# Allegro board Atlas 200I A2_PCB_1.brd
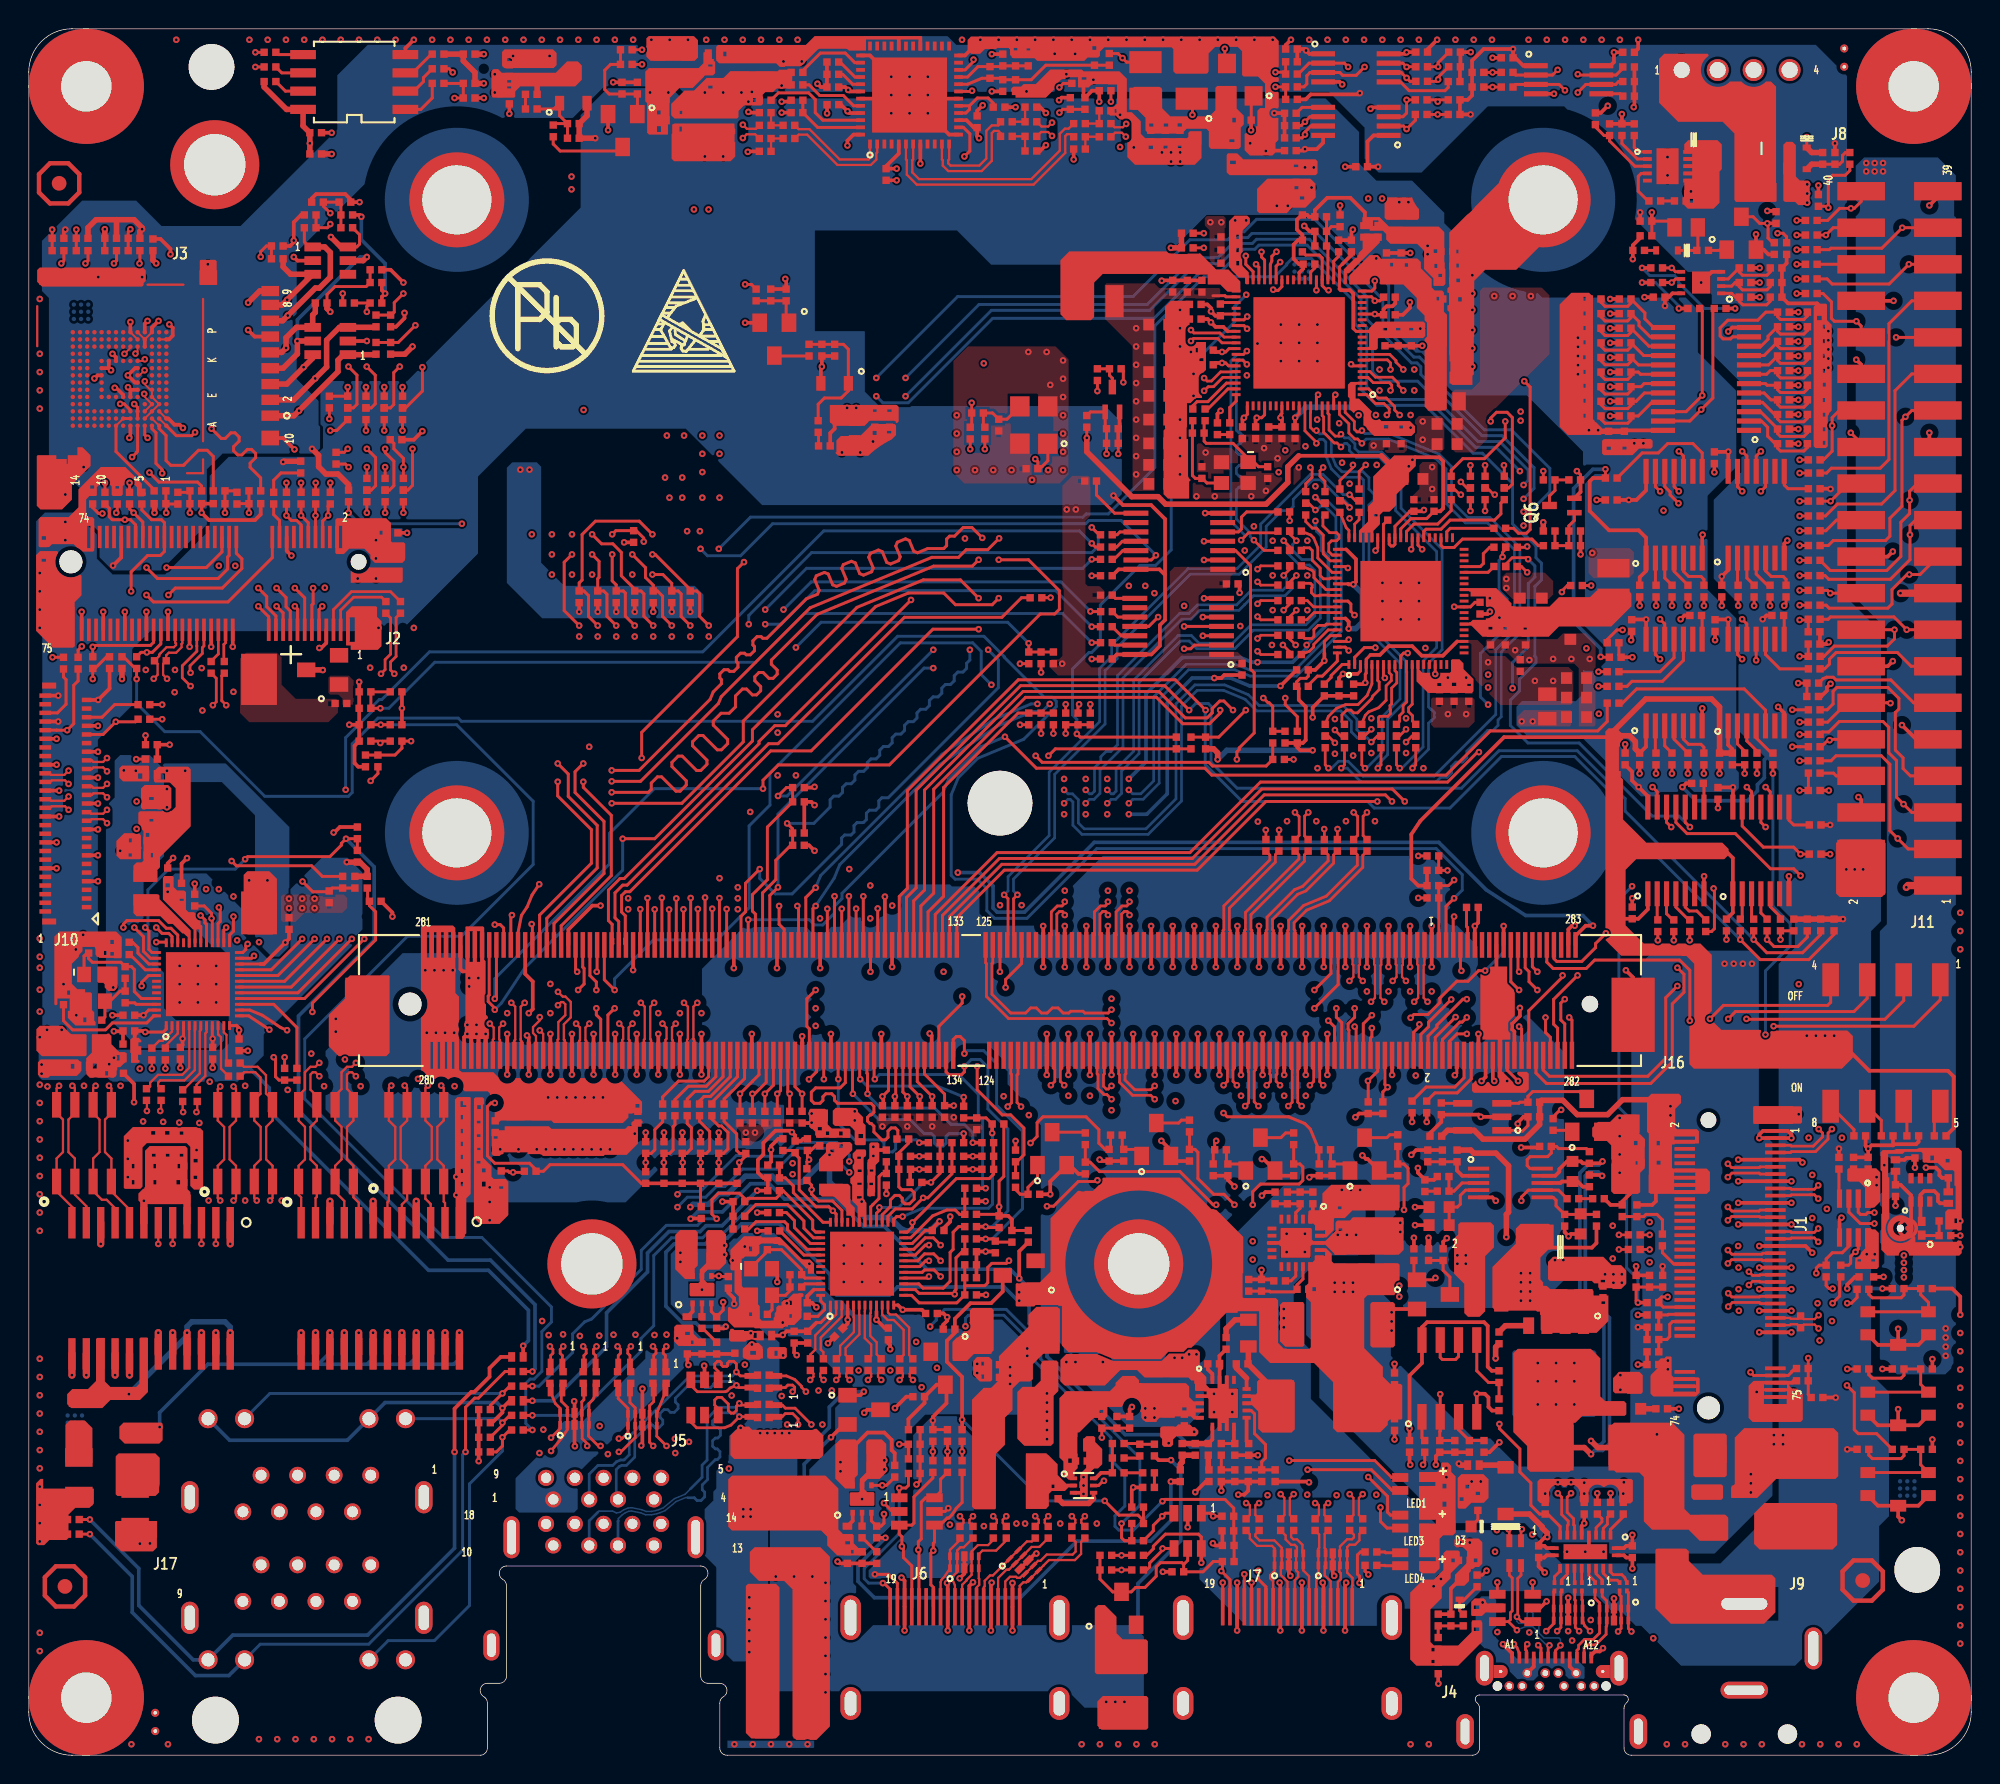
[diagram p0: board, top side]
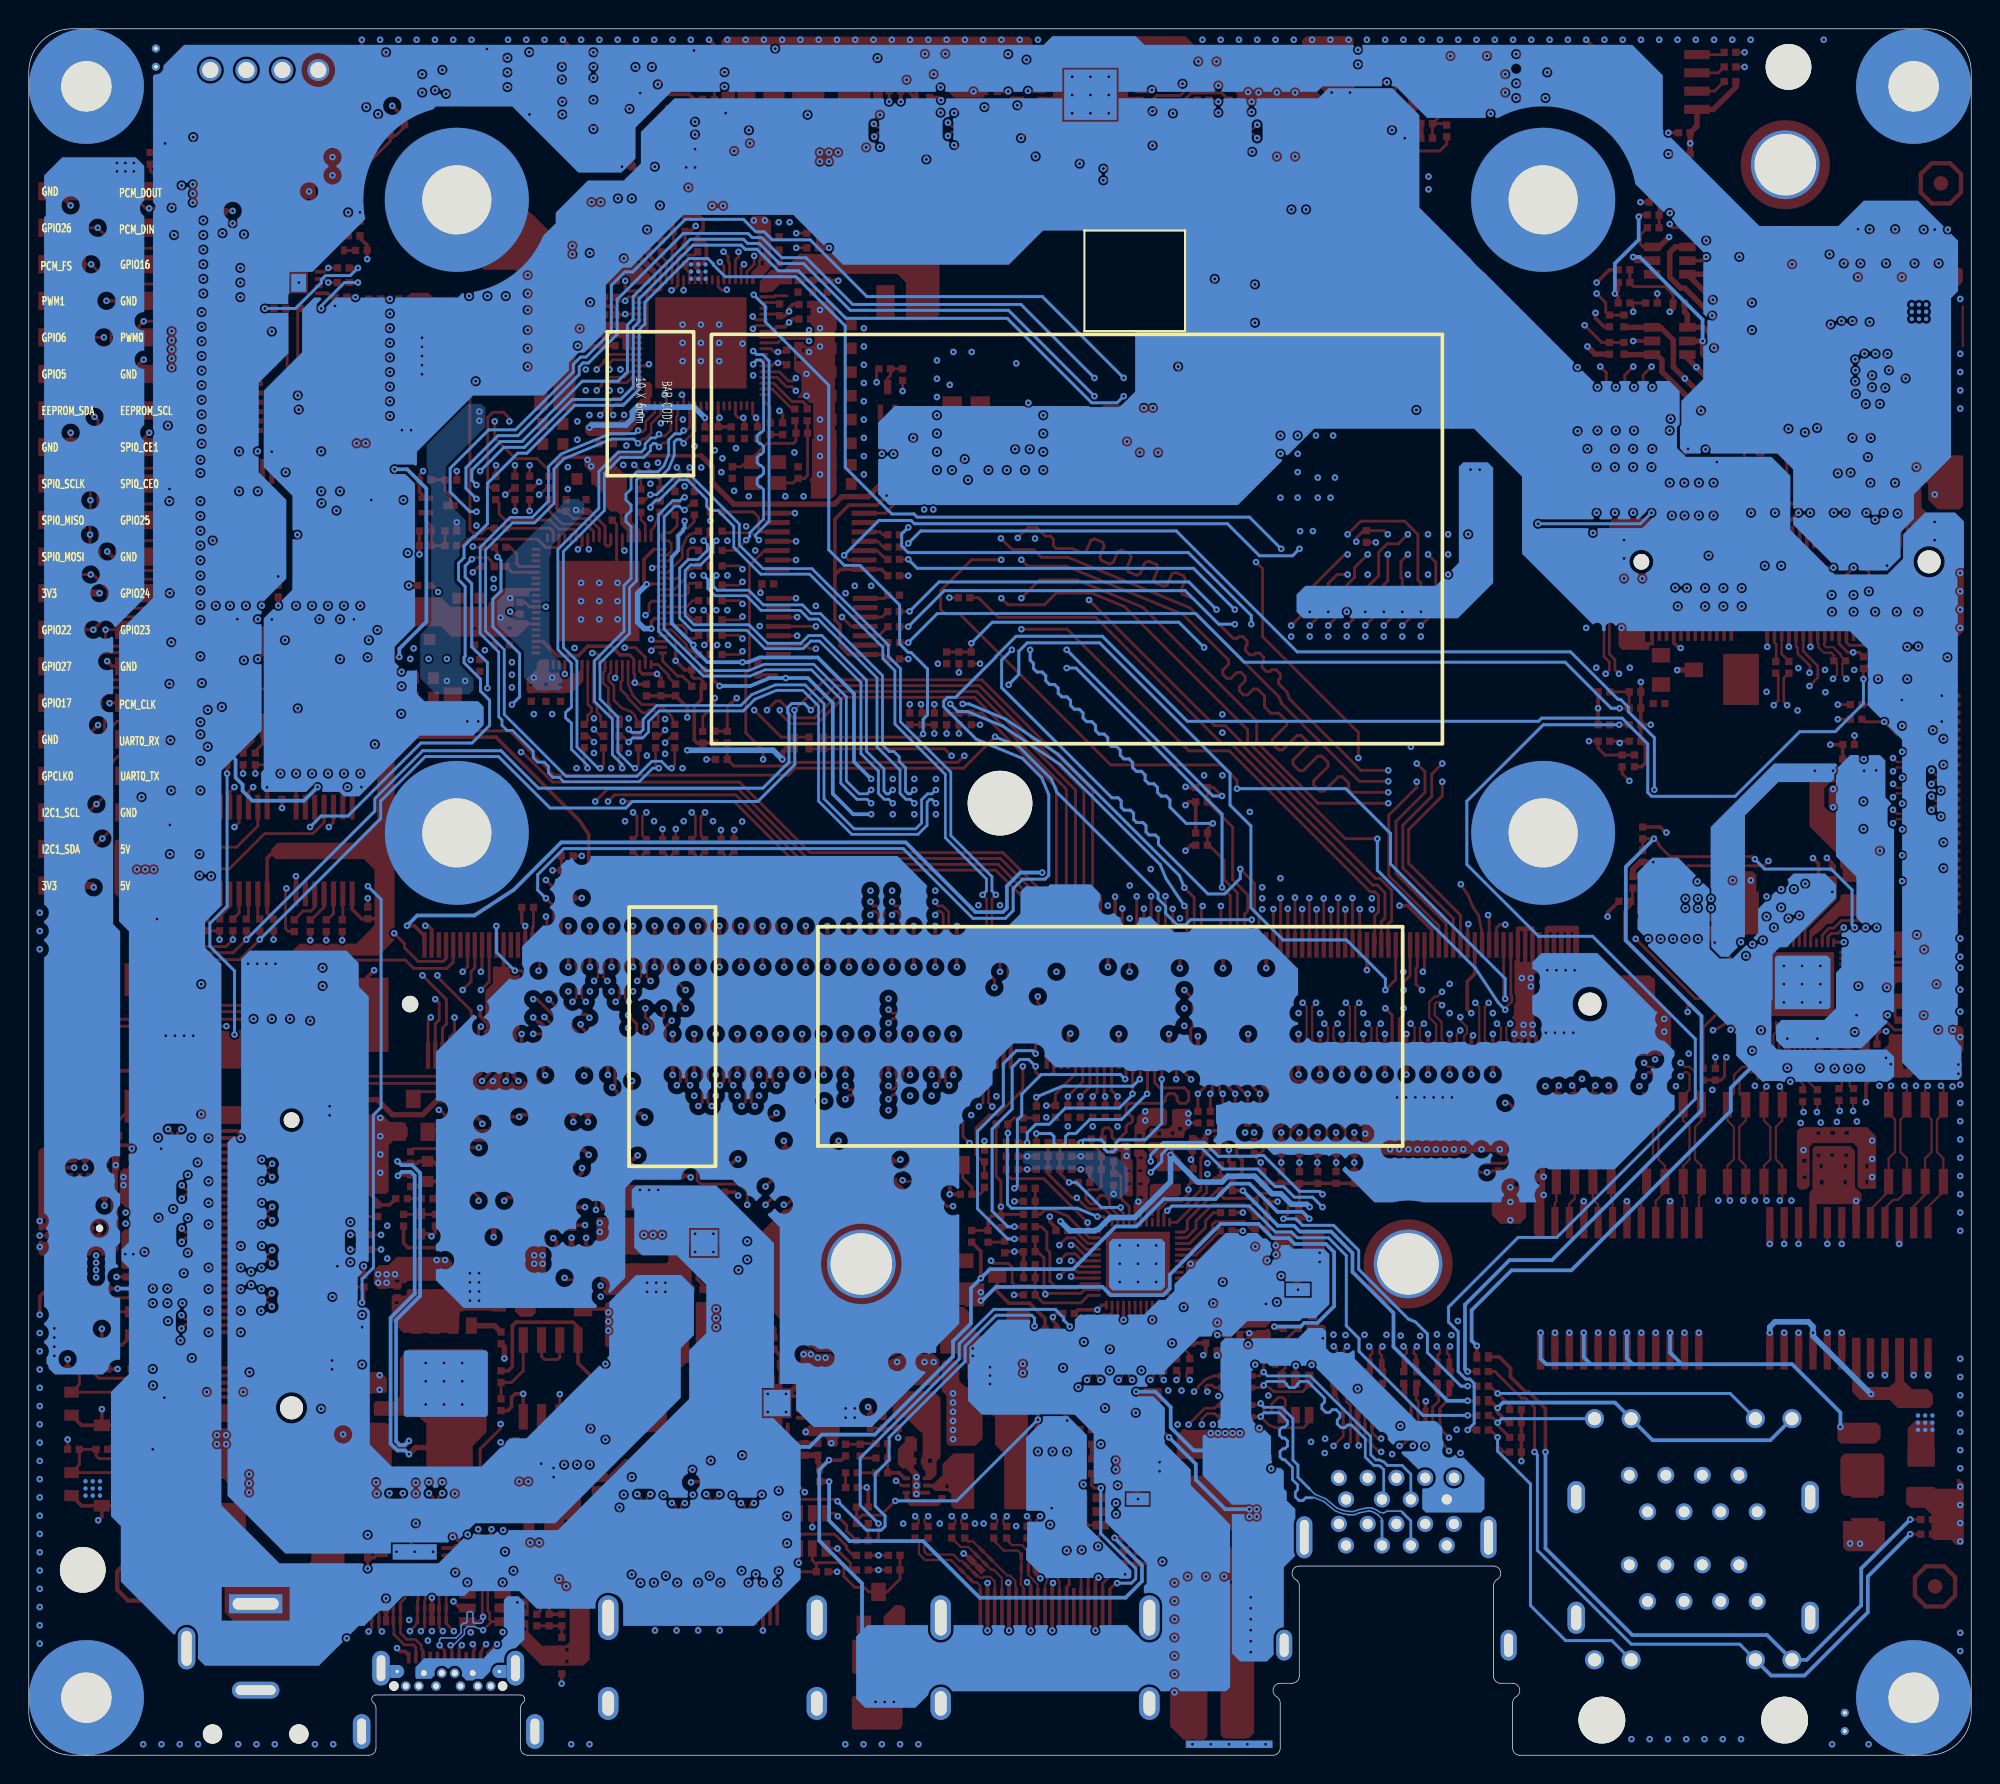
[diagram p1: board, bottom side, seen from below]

Outline 135 x 120 mm; copper layers: TOP, ART02, ART03, ART04, ART05, BOTTOM. Coordinates in mm from the lower left corner of the outline.
Outline path: 0,117 0,3 arc(0.88,0.88) 3,0 31.38,0 arc(31.73,0.15) 31.87,0.5 31.87,3.63 arc(31.81,3.88) 31.63,4.07 arc(31.39,4.63) 31.87,5 32.7,5 arc(33.05,5.15) 33.2,5.5 33.2,11.78 arc(33.13,12.03) 32.95,12.22 arc(32.72,12.78) 33.2,13.15 46.7,13.15 arc(47.18,12.78) 46.95,12.22 arc(46.77,12.03) 46.7,11.78 46.7,5.5 arc(46.85,5.15) 47.2,5 48.02,5 arc(48.51,4.63) 48.27,4.07 arc(48.09,3.88) 48.02,3.63 48.02,0.5 arc(48.17,0.15) 48.52,0 100.33,0 arc(100.68,0.15) 100.83,0.5 100.83,3.27 arc(100.78,3.48) 100.64,3.66 arc(100.55,3.99) 100.83,4.19 110.87,4.19 arc(111.15,3.99) 111.06,3.66 arc(110.92,3.48) 110.87,3.27 110.87,0.5 arc(111.02,0.15) 111.37,0 132,0 arc(134.12,0.88) 135,3 135,117 arc(134.12,119.12) 132,120 3,120 arc(0.88,119.12) 0,117

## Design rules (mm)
constraint set DEFAULT: min track width 0.203
net group $12N40858: nets $12N40858 $12N40901
net group $47N4481: nets $47N4481 /CLKREQ_WIFI
net group $47N43343: nets $47N43343 USB2_2_DP
net group $47N43374: nets $47N43374 USB2_2_DN
net group /EMMC_RESET: nets /EMMC_RESET /EMMC_RESET_R
net group /LED_PHY0_ACT: nets $19N46347 /LED_PHY0_ACT
net group /LED_PHY0_LINK: nets $19N73517 /LED_PHY0_LINK
net group /LED_PHY1_ACT: nets $19N48970 /LED_PHY1_ACT
net group /LED_PHY1_LINK: nets $19N48969 /LED_PHY1_LINK
net group /PERST_M2: nets $51N193077 /PERST_M2
net group /PERST_M2_R: nets $46N95508 /PERST_M2_R
net group /PERST_WIFI: nets $51N185068 /PERST_WIFI
net group /PERST_WIFI_R: nets $51N185799 /PERST_WIFI_R
net group /PEWAKE_WIFI: nets $51N189030 /PEWAKE_WIFI
net group /WAKE_PHY0: nets $51N189029 /WAKE_PHY0
net group /WAKE_PHY1: nets $51N189028 /WAKE_PHY1
net group /WAKE_UART3: nets $47N36111 /WAKE_UART3
net group AC_MICBIAS0: nets $16N50739 AC_MICBIAS0
net group CARD_DETECT: nets CARD_DETECT SDIO_DETECT
net group CLK_100M_OSC: nets $17N59162 CLK_100M_OSC
net group DEVSLP_M2: nets $46N95153 DEVSLP_M2
net group DIFFUSB2_1: nets USB2_1_DN USB2_1_DP
net group DIFFUSB2_3: nets USB2_3_DN USB2_3_DP
net group DIFFUSB2_3_HUB0: nets USB2_3_HUB0_DN USB2_3_HUB0_DP
net group DIFFUSB2_3_HUB1: nets USB2_3_HUB1_DN USB2_3_HUB1_DP
net group DIFFUSB3_2_TX: nets USB3_2_TX_N USB3_2_TX_P
net group DIFFUSB3_3_RX_HUB0: nets USB3_3_RX_HUB0_N USB3_3_RX_HUB0_P
net group DIFFUSB3_3_RX_HUB1: nets USB3_3_RX_HUB1_N USB3_3_RX_HUB1_P
net group DIFFUSB3_3_TX_HUB0: nets USB3_3_TX_HUB0_N USB3_3_TX_HUB0_P
net group DIFFUSB3_3_TX_HUB1: nets USB3_3_TX_HUB1_N USB3_3_TX_HUB1_P
net group DIFFUSB3_3_TYPEA1_HUB0_TX1: nets USB3_3_TYPEA1_HUB0_TX1_N USB3_3_TYPEA1_HUB0_TX1_P
net group DIFFUSB3_3_TYPEA1_HUB1_RX1: nets USB3_3_TYPEA1_HUB1_RX1_N USB3_3_TYPEA1_HUB1_RX1_P
net group DIFFUSB3_3_TYPEA1_HUB1_TX1: nets USB3_3_TYPEA1_HUB1_TX1_N USB3_3_TYPEA1_HUB1_TX1_P
net group DIFFUSB3_3_TYPEA1_HUB_RX1: nets USB3_3_TYPEA1_HUB_RX1_N USB3_3_TYPEA1_HUB_RX1_P
net group DIFFUSB3_3_TYPEA2_HUB0_RX2: nets USB3_3_TYPEA2_HUB0_RX2_N USB3_3_TYPEA2_HUB0_RX2_P
net group DIFFUSB3_3_TYPEA2_HUB0_TX2: nets USB3_3_TYPEA2_HUB0_TX2_N USB3_3_TYPEA2_HUB0_TX2_P
net group DIFFUSB3_3_TYPEA2_HUB1_RX2: nets USB3_3_TYPEA2_HUB1_RX2_N USB3_3_TYPEA2_HUB1_RX2_P
net group DIFFUSB3_3_TYPEA2_HUB1_TX2: nets USB3_3_TYPEA2_HUB1_TX2_N USB3_3_TYPEA2_HUB1_TX2_P
net group DIFFUSB3_3_TYPEA2_HUB_RX2: nets USB3_3_TYPEA2_HUB_RX2_N USB3_3_TYPEA2_HUB_RX2_P
net group DIFFUSB3_3_TYPEA2_HUB_TX2: nets USB3_3_TYPEA2_HUB_TX2_N USB3_3_TYPEA2_HUB_TX2_P
net group DIFFUSB20_TYPEA2_HUB1: nets USB20_TYPEA2_HUB1_DN USB20_TYPEA2_HUB1_DP
net group DIFFUSB_TYPEC_CON: nets USB_TYPEC_CON_DN USB_TYPEC_CON_DP
net group DSI_I2C_INT: nets $51N189031 DSI_I2C_INT
net group DSI_I2C_INT_R: nets $49N38251 DSI_I2C_INT_R
net group FAN_STA: nets $18N13057 FAN_STA
net group GATE_24711: nets $20N81774 GATE_24711
net group GPIO13: nets $51N194833 GPIO13
net group GPIO16: nets $51N171792 GPIO16
net group GPIO17_3V3: nets $49N29598 GPIO17_3V3
net group GPIO22: nets $51N172159 GPIO22
net group GPIO22_3V3: nets $49N16355 GPIO22_3V3
net group GPIO23: nets $51N172500 GPIO23
net group GPIO23_3V3: nets $49N16315 GPIO23_3V3
net group GPIO24: nets $51N176455 GPIO24
net group GPIO24_3V3: nets $49N16316 GPIO24_3V3
net group GPIO25: nets $51N176454 GPIO25
net group GPIO26: nets $51N176453 GPIO26
net group GPIO26_3V3: nets $49N16328 GPIO26_3V3
net group GPIO27: nets $51N194878 GPIO27
net group HDMI0_CEC: nets HDMI0_CEC HDMI0_TX_CEC
net group HDMI0_SCL: nets HDMI0_SCL HDMI0_TX_DDC_SCL_C
net group HDMI0_SDA: nets HDMI0_SDA HDMI0_TX_DDC_SDA_C
net group HDMI0_TXC_N: nets HDMI0_TXC_C_N HDMI0_TXC_N
net group HDMI0_TXC_P: nets HDMI0_TXC_C_P HDMI0_TXC_P
net group HDMI1_CEC: nets HDMI1_CEC HDMI1_TX_CEC
net group HDMI1_SCL: nets HDMI1_SCL HDMI1_TX_DDC_SCL_C
net group HDMI1_SDA: nets HDMI1_SDA HDMI1_TX_DDC_SDA_C
net group HDMI1_TX0_C_N: nets HDMI1_TX0_C_N HDMI1_TX0_N
net group HDMI1_TX0_C_P: nets HDMI1_TX0_C_P HDMI1_TX0_P
net group HDMI1_TX1_C_N: nets HDMI1_TX1_C_N HDMI1_TX1_N
net group HDMI1_TX1_C_P: nets HDMI1_TX1_C_P HDMI1_TX1_P
net group HDMI1_TX2_C_N: nets HDMI1_TX2_C_N HDMI1_TX2_N
net group HDMI1_TX2_C_P: nets HDMI1_TX2_C_P HDMI1_TX2_P
net group HDMI1_TXC_C_N: nets HDMI1_TXC_C_N HDMI1_TXC_N
net group HDMI1_TXC_C_P: nets HDMI1_TXC_C_P HDMI1_TXC_P
net group I2C6_SCL: nets $49N16337 I2C6_SCL
net group I2C6_SDA: nets $49N16335 I2C6_SDA
net group I2C7_SCL: nets $49N18560 I2C7_SCL
net group I2C7_SCL_R: nets $49N16308 I2C7_SCL_R
net group I2C7_SDA: nets $49N18561 I2C7_SDA
net group I2C7_SDA_R: nets $49N16307 I2C7_SDA_R
net group I2S0_BCLK_R: nets $49N16347 I2S0_BCLK_R
net group I2S0_LRCK: nets $51N204476 I2S0_LRCK
net group I2S0_LRCK_R: nets $49N16344 I2S0_LRCK_R
net group I2S0_MCLK: nets $51N196013 I2S0_MCLK
net group I2S0_MISO: nets $51N204970 I2S0_MISO
net group I2S0_MISO_R: nets $49N16346 I2S0_MISO_R
net group I2S0_MOSI: nets $51N205764 I2S0_MOSI
net group I2S0_MOSI_R: nets $49N16348 I2S0_MOSI_R
net group I2S1_BCLK: nets $47N8328 I2S1_BCLK
net group I2S1_LRCK: nets $47N8362 I2S1_LRCK
net group I2S1_MCLK: nets $51N196011 I2S1_MCLK
net group I2S1_MCLK_R: nets $49N25997 I2S1_MCLK_R
net group I2S1_MISO: nets $47N12203 I2S1_MISO
net group I2S1_MOSI: nets $47N12239 I2S1_MOSI
net group LED_G: nets $45N7207 LED_G
net group LED_HEALTHY_G: nets $45N4598 LED_HEALTHY_G
net group LED_HEALTHY_R: nets $45N4597 LED_HEALTHY_R
net group LED_R: nets $45N7206 LED_R
net group M2_TYPE: nets $46N92195 M2_TYPE
net group MIPI_DSI_SCL: nets $49N18573 MIPI_DSI_SCL
net group MIPI_DSI_SCL_R: nets $49N8793 MIPI_DSI_SCL_R
net group MIPI_DSI_SDA: nets $49N18574 MIPI_DSI_SDA
net group MIPI_DSI_SDA_R: nets $49N8755 MIPI_DSI_SDA_R
net group MIPI_GPIO: nets $51N175745 MIPI_GPIO
net group MIPI_GPIO_R: nets $49N38048 MIPI_GPIO_R
net group PCIE_RX_N/SATA_B_P: nets PCIE_RX_N/SATA_B_P SERDES0_RX_N
net group PCIE_RX_P/SATA_B_N: nets PCIE_RX_P/SATA_B_N SERDES0_RX_P
net group PWM1: nets $51N193392 PWM1
net group PWM1_R: nets $49N16343 PWM1_R
net group RGMII0_MDCK: nets $7N42494 RGMII0_MDCK
net group RGMII0_MDIO: nets $7N42485 RGMII0_MDIO
net group RGMII0_RST: nets $51N184427 RGMII0_RST
net group RGMII0_RST_R: nets $51N185453 RGMII0_RST_R
net group RGMII0_RXCK: nets RGMII0_RXCK RGMII_CLK_PHY0
net group RGMII0_RXD0: nets RGMII0_RXD0 RGMII_PHY0_D0
net group RGMII0_RXD1: nets RGMII0_RXD1 RGMII_PHY0_D1
net group RGMII0_RXD2: nets RGMII0_RXD2 RGMII_PHY0_D2
net group RGMII0_RXD3: nets RGMII0_RXD3 RGMII_PHY0_D3
net group RGMII0_RXDV: nets RGMII0_RXDV RGMII_DV_PHY0
net group RGMII1_MDCK: nets $8N37120 RGMII1_MDCK
net group RGMII1_MDIO: nets $8N37111 RGMII1_MDIO
net group RGMII1_RST: nets $51N184426 RGMII1_RST
net group RGMII1_RST_R: nets $51N185452 RGMII1_RST_R
net group RGMII1_RXCK: nets RGMII1_RXCK RGMII_CLK_PHY1
net group RGMII1_RXD0: nets RGMII1_RXD0 RGMII_PHY1_D0
net group RGMII1_RXD1: nets RGMII1_RXD1 RGMII_PHY1_D1
net group RGMII1_RXD2: nets RGMII1_RXD2 RGMII_PHY1_D2
net group RGMII1_RXD3: nets RGMII1_RXD3 RGMII_PHY1_D3
net group RGMII1_RXDV: nets RGMII1_RXDV RGMII_DV_PHY1
net group SERDES1_RX: nets SERDES1_RX_N SERDES1_RX_P
net group SERDES2_RX: nets SERDES2_RX_N SERDES2_RX_P
net group SERDES3_RX: nets SERDES3_RX_N SERDES3_RX_P
net group SERDES4_RX: nets SERDES4_RX_N SERDES4_RX_P
net group SERDES4_TX_N: nets $47N40951 SERDES4_TX_N
net group SERDES4_TX_P: nets $47N40952 SERDES4_TX_P
net group SPI0_CLK: nets $51N199818 SPI0_CLK
net group SPI0_CLK_R: nets $49N16313 SPI0_CLK_R
net group SPI0_CS0: nets $51N198291 SPI0_CS0
net group SPI0_CS0_R: nets $49N16317 SPI0_CS0_R
net group SPI0_MISO: nets $51N199282 SPI0_MISO
net group SPI0_MISO_R: nets $49N16312 SPI0_MISO_R
net group SPI0_MOSI: nets $51N198558 SPI0_MOSI
net group SPI0_MOSI_R: nets $49N16311 SPI0_MOSI_R
net group SPI_CS_HUB: nets $56N3511 SPI_CS_HUB
net group SPI_MISO_HUB: nets $56N3501 SPI_MISO_HUB
net group SPI_MOSI_HUB: nets $56N3513 SPI_MOSI_HUB
net group SPI_SCK_HUB: nets $56N3505 SPI_SCK_HUB
net group SYS_RST_IN: nets SYS_RST_IN SYS_RST_IN_R
net group TAISHAN_POWEROFF_IN: nets TAISHAN_POWEROFF_IN TAISHAN_POWEROFF_IN_R
net group UART0_RX_R: nets $49N16309 UART0_RX_R
net group UART2_CTX: nets $51N196657 UART2_CTX
net group UART2_CTX_R: nets $49N34084 UART2_CTX_R
net group UART2_RTX: nets $51N196656 UART2_RTX
net group UART2_RTX_R: nets $49N34222 UART2_RTX_R
net group UART3_CTX: nets $47N4444 UART3_CTX
net group UART3_RTX: nets $47N18593 UART3_RTX
net group UART3_RX: nets $47N4445 UART3_RX
net group UART3_TX: nets $47N17143 UART3_TX
net group UPDATE_MODE: nets UPDATE_MODE UPDATE_MODE_R
net group USB3_2_RX_: nets USB3_2_RX_N USB3_2_RX_P
net group USB3_3_RX_: nets USB3_3_RX_N USB3_3_RX_P
net group USB3_3_TX_: nets USB3_3_TX_N USB3_3_TX_P
net group USB3_SW_SEL: nets $12N40909 USB3_SW_SEL
net group USB20_TYPEA1_HUB0_D: nets USB20_TYPEA1_HUB0_DN USB20_TYPEA1_HUB0_DP
net group USB20_TYPEA1_HUB1_D: nets USB20_TYPEA1_HUB1_DN USB20_TYPEA1_HUB1_DP
net group USB20_TYPEA2_HUB0_D: nets USB20_TYPEA2_HUB0_DN USB20_TYPEA2_HUB0_DP
net group V_12V0_SENSE: nets $20N78430 V_12V0_SENSE
net group XTAL_OUT_PHY0: nets $7N42508 XTAL_OUT_PHY0
net group /PEWAKE_WIFI_R: nets $47N4437 $51N188619 /PEWAKE_WIFI_R
net group /WAKE_PHY0_R: nets $7N42503 $51N188624 /WAKE_PHY0_R
net group /WAKE_PHY1_R: nets $8N37128 $51N188623 /WAKE_PHY1_R
net group CLK_100M_BUF_M2_L1_P: nets CLK_100M_BUF_M2_L1_P
net group HDMI0_TX0_C_N: nets HDMI0_TX0_N
net group HDMI0_TX0_C_P: nets HDMI0_TX0_P
net group HDMI0_TX1_C_N: nets HDMI0_TX1_N
net group HDMI0_TX1_C_P: nets HDMI0_TX1_P
net group HDMI0_TX2_C_N: nets HDMI0_TX2_N
net group HDMI0_TX2_C_P: nets HDMI0_TX2_P
net group I2C8_SCL: nets $47N11243 $52N846 I2C8_SCL
net group I2C8_SCL_R: nets $52N827 $52N845 $52N2707 I2C8_SCL_R
net group I2C8_SDA: nets $47N11242 $52N847 I2C8_SDA
net group I2C8_SDA_R: nets $52N828 $52N844 $52N2706 I2C8_SDA_R
net group I2S0: nets I2S0_BCLK
net group PHY: nets $19N66318 $19N66421 $19N66917 $19N67094 PHY0_MDI0_N PHY0_MDI0_P PHY0_MDI1_N PHY0_MDI1_P PHY0_MDI2_N PHY0_MDI2_P PHY0_MDI3_N PHY0_MDI3_P PHY1_MDI0_N PHY1_MDI0_P PHY1_MDI1_N PHY1_MDI1_P PHY1_MDI2_N PHY1_MDI2_P PHY1_MDI3_N PHY1_MDI3_P
net group RGMII0-TXD: nets RGMII0_TXCK RGMII0_TXD0 RGMII0_TXD1 RGMII0_TXD2 RGMII0_TXD3 RGMII0_TXEN
net group SPI2: nets $45N4601 $45N4602 $45N7210 $45N7211 SPI2_CLK SPI2_CS0 SPI2_MISO SPI2_MOSI
net group SPI_HUB0: nets SPI_CLK_HUB0 SPI_CS_HUB0 SPI_MISO_HUB0 SPI_MOSI_HUB0
net group SPI_HUB1: nets SPI_CS_HUB1 SPI_MISO_HUB1 SPI_MOSI_HUB1 SPI_SCK_HUB1
net group USB3_1_CONN_TX_N: nets USB3_1_CONN_TX_N
net group USB3_1_CONN_TX_P: nets USB3_1_CONN_TX_P
net group USB3_1_TX_N: nets $12N55491
net group USB3_1_TX_P: nets $12N55490
net group USB20_TYPEA1_HUB_DN: nets USB2_1_CONN_DN
net group USB20_TYPEA1_HUB_DP: nets USB2_1_CONN_DP
net group USB20_TYPEA2_HUB_DN: nets USB2_2_CONN_DN
net group USB20_TYPEA2_HUB_DP: nets USB2_2_CONN_DP
nets with their own width: min track width 0.203; nets USB_12M_X0_HUB1 USB_12M_XI_HUB1 USB_25M_XI_HUB1 USB_25M_XO_HUB1

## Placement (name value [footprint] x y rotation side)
C1  220nF  [SC0402]  92.08 63.25 90 top
C2  220nF  [SC0402]  90.04 63.25 90 top
C3  220nF  [SC0402]  90.95 63.25 90 top
C4  22uF  [SC1206-TF]  52.45 10.81 0 top
C5  22uF  [SC1206-TF]  52.45 8.61 0 top
C6  220nF  [SC0402]  93.01 63.25 90 top
C7  22uF  [SC1206-TF]  52.45 1.99 0 top
C8  22uF  [SC1206-TF]  52.45 6.4 0 top
C9  100nF  [SC0402-PB]  1.02 83.82 90 top
C10  100nF  [SC0402-PB]  112.47 42.55 0 top
C11  22uF  [SC0805-TD]  112.27 43.89 0 top
C12  10uF  [SC0603-TD]  1.52 86.36 270 top
C13  10nF  [SC0402-PB]  80.01 112.54 90 top
C14  100nF  [SC0402-PB]  112.47 41.18 0 top
C15  100nF  [SC0402-PB]  69.46 117.83 270 top
C16  22uF  [SC0805-TD]  112.27 39.73 0 top
C17  100nF  [SC0402-PB]  74.89 81.98 0 top
C18  100nF  [SC0402-PB]  112.88 27.16 0 top
C19  22uF  [SC0805-TD]  88.9 29.11 180 top
C20  22uF  [SC0805-TD]  112.4 25.76 0 top
C21  220nF  [SC0402]  86.88 63.25 90 top
C22  220nF  [SC0402]  85.98 63.25 90 top
C23  22uF  [SC1206-TF]  52.45 4.2 0 top
C24  22uF  [SC1206-TF]  49.85 20.04 90 top
C25  220nF  [SC0402]  88.92 63.25 90 top
C26  220nF  [SC0402]  88.01 63.25 90 top
C27  22uF  [SC1206-TF]  53.88 14.96 270 top
C28  22uF  [SC1206-TF]  51.68 14.96 270 top
C29  22uF  [SC0805-TD]  88.9 30.86 180 top
C30  22uF  [SC1206-TF]  52.06 20.04 90 top
C31  22uF  [SC1206-TF]  54.26 20.04 90 top
C32  10uF  [SC0805-TD]  40.85 43.82 90 top
C33  100nF  [SC0402-PB]  83.64 81.41 0 top
C34  100nF  [SC0402-PB]  111.71 32.95 90 top
C35  10uF  [SC0805-TD]  70.08 26.75 0 top
C36  100nF  [SC0402-PB]  128.22 33.66 90 top
C37  100nF  [SC0402-PB]  25.25 84.96 180 top
C38  100nF  [SC0402-PB]  127.2 33.66 90 top
C39  100nF  [SC0402-PB]  126.82 41.15 270 top
C40  10uF  [SC0603-TD]  25.25 82.8 90 top
C41  220nF  [SC0402]  13.59 75.62 90 top
C42  220nF  [SC0402]  12.67 75.62 90 top
C43  100nF  [SC0402-PB]  127.84 41.15 270 top
C44  5pF  [SC0402-PA]  61.66 39.81 180 top
C45  10pF  [SC0402]  23.37 70.48 0 top
C46  30pF  [SC0402-PA]  4.57 55.75 0 top
C47  30pF  [SC0402-PA]  4.67 51.09 0 top
C48  10uF  [SC0603-TD]  4.27 49.28 0 top
C49  100nF  [SC0402-PB]  6.95 50.34 0 top
C50  100nF  [SC0402-PB]  6.95 49.43 0 top
C51  1uF  [SC0402-PC]  14.61 49.38 90 top
C52  100nF  [SC0402-PB]  6.95 51.44 0 top
C53  100nF  [SC0402-PB]  12.78 48.79 90 top
C54  1uF  [SC0402-PC]  7.82 63.58 0 top
C55  10uF  [SC0402-PD]  8.53 65.74 270 top
C56  1uF  [SC0402-PC]  10.53 48.79 90 top
C57  4.7uF  [SC0402-PC]  18.08 57.81 270 top
C58  100nF  [SC0402-PB]  7.82 62.56 0 top
C59  10uF  [SC0603-TD]  1.91 48.64 270 top
C60  100nF  [SC0402-PB]  6.17 47.4 180 top
C61  100nF  [SC0402-PB]  10.62 60.2 270 top
C62  1uF  [SC0402-PC]  9.65 61.26 270 top
C63  10nF  [SC0402-PB]  32.84 40.21 90 top
C64  30pF  [SC0402-PA]  50.93 35.14 180 top
C65  30pF  [SC0402-PA]  50.93 30.64 0 top
C66  4.7uF  [SC0402-PC]  55.88 42.77 270 top
C67  100nF  [SC0402-PB]  56.82 42.77 270 top
C68  10pF  [SC0402]  65.46 35 180 top
C69  10uF  [SC0402-PD]  49.48 27.94 0 top
C70  1uF  [SC0402-PC]  63.2 36.47 180 top
C71  100nF  [SC0402-PB]  53.7 31.45 0 top
C72  100nF  [SC0402-PB]  56.28 29.38 45 top
C73  1uF  [SC0402-PC]  59.74 29.28 90 top
C74  10uF  [SC0603-TD]  49.3 29.87 270 top
C75  100nF  [SC0402-PB]  62.74 30.71 180 top
C76  100nF  [SC0402-PB]  54.13 29.06 90 top
C77  1uF  [SC0402-PC]  53.19 29.06 90 top
C78  10uF  [SC0603-TD]  55.86 44.47 0 top
C79  100nF  [SC0402-PB]  58.14 40.97 180 top
C80  100nF  [SC0402-PB]  58.14 40.05 180 top
C81  1uF  [SC0402-PC]  58.14 39.11 180 top
C82  10nF  [SC0402-PB]  59.6 41.66 270 top
C83  10nF  [SC0402-PB]  55.12 97.66 270 top
C84  10nF  [SC0402-PB]  37.85 113.41 0 top
C85  1uF  [SC0402-PC]  41.23 115.87 90 top
C86  22pF*  [SC0402-PA]  25.53 91.44 180 top
C87  10nF*  [SC0402-PB]  20.89 94.06 90 top
C88  100nF*  [SC0402-PB]  8.63 104.99 90 top
C89  100nF  [SC0402-PB]  55.3 91.01 0 top
C90  1uF  [SC0402-PC]  52.64 101.5 90 top
C91  100nF*  [SC0402-PB]  34.92 115.44 0 top
C92  10nF  [SC0402-PB]  3.1 16.38 180 top
C93  10nF  [SC0402-PB]  31.67 23.11 180 top
C94  10uF  [SC0603-TD]  81.79 112.34 0 top
C95  10pF  [SC0402]  74.07 117.88 90 top
C96  100nF  [SC0402-PB]  88.04 85.08 0 top
C97  100nF  [SC0402-PB]  88.04 83.74 0 top
C98  10nF  [SC0402-PB]  59.82 92.71 90 top
C99  100nF  [SC0402-PB]  58.8 92.71 90 top
C100  10uF  [SC0603-TD]  57.4 92.08 90 top
C101  10uF  [SC0603-TD]  34.92 117.22 270 top
C102  100nF  [SC0402-PB]  33.4 115.19 90 top
C103  10nF  [SC0402-PB]  33.4 117.09 270 top
C104  100nF*  [SC0402-PB]  21.97 107.95 0 top
C105  100nF  [SC0402-PB]  90.09 86.61 270 top
C106  100nF  [SC0402-PB]  88.75 86.61 270 top
C107  100nF*  [SC0402-PB]  88.75 87.43 90 top
C108  100nF*  [SC0402-PB]  90.09 87.43 90 top
C109  5pF  [SC0402-PA]  11.53 59.44 90 top
C110  100nF*  [SC0402-PB]  87.22 83.74 180 top
C111  100nF*  [SC0402-PB]  87.22 85.08 180 top
C112  100nF*  [SC0402-PB]  87.22 82.67 0 top
C113  100nF  [SC0402-PB]  108.1 17.17 270 top
C114  100nF  [SC0402-PB]  88.04 82.67 180 top
C115  100nF  [SC0402-PB]  111.45 14.15 90 top
C116  22pF  [SC0402-PA]  97.96 6.07 90 top
C117  1uF  [SC0402-PC]  99.77 13.55 180 top
C118  100nF  [SC0402-PB]  97.96 9.4 90 top
C119  100nF  [SC0402-PB]  95.96 21.46 270 top
C120  100nF  [SC0402-PB]  98.06 21.46 90 top
C121  5pF  [SC0402-PA]  49.43 44.35 270 top
C122  5pF  [SC0402-PA]  50.29 44.35 270 top
C123  4.7uF  [SC0603-TD]  46.79 34.54 180 top
C124  4.7uF  [SC0603-TD]  46.79 35.9 180 top
C125  4.7uF  [SC0603-TD]  57.91 19.99 180 top
C126  4.7uF  [SC0603-TD]  57.91 21.34 180 top
C127  100nF  [SC0402-PB]  46.79 28.3 270 top
C128  5pF  [SC0402-PA]  51.16 44.35 270 top
C129  100nF  [SC0402-PB]  109.98 87.25 0 top
C130  100nF  [SC0402-PB]  117.15 90.19 90 top
C131  100nF  [SC0402-PB]  111.96 80.92 270 top
C132  100nF  [SC0402-PB]  117.66 80.92 270 top
C133  100nF  [SC0402-PB]  87.68 111.53 180 top
C134  100nF  [SC0402-PB]  57.91 13.74 270 top
C135  5pF  [SC0402-PA]  52.02 44.35 270 top
C136  100nF  [SC0402-PB]  92.63 110.41 0 top
C137  100nF  [SC0402-PB]  111.19 118.36 0 top
C138  100nF  [SC0402-PB]  102.75 117.98 0 top
C139  100nF  [SC0402-PB]  74.89 76.19 0 top
C140  100nF  [SC0402-PB]  117.2 78.52 90 top
C141  100nF  [SC0402-PB]  61.85 24.92 180 top
C142  220nF  [SC0402]  61.54 20.6 180 top
C143  100nF  [SC0402-PB]  63.96 29.61 180 top
C144  100nF  [SC0402-PB]  79.86 12.75 180 top
C145  220nF  [SC0402]  83.34 15.6 180 top
C146  100nF  [SC0402-PB]  77.06 17.25 180 top
C147  100nF  [SC0402-PB]  133.17 37.13 0 top
C148  220pF  [SC0402-PA]  131.5 41.51 0 top
C149  220pF  [SC0402-PA]  133.41 40.54 90 top
C150  5pF  [SC0402-PA]  52.88 44.35 270 top
C151  5pF  [SC0402-PA]  53.75 44.35 270 top
C152  100nF  [SC0402-PB]  55.88 115.95 180 top
C153  10uF  [SC0603-TD]  43.81 117.47 90 top
C154  5pF  [SC0402-PA]  59.33 44.75 270 top
C155  22uF  [SC0805-TD]  48.39 113.54 90 top
C156  22uF  [SC0805-TD]  49.4 117.35 270 top
C157  100nF  [SC0402-PB]  59.58 109.87 270 top
C158  100nF  [SC0402-PB]  55.89 114.73 180 top
C159  5pF  [SC0402-PA]  60.19 44.75 270 top
C160  5pF  [SC0402-PA]  61.06 44.75 270 top
C161  100nF  [SC0402-PB]  65.91 113.54 90 top
C162  100nF  [SC0402-PB]  44.58 114.17 0 top
C163  22uF  [SC0805-TD]  46.48 113.54 90 top
C164  100nF  [SC0402-PB]  47.37 116.71 270 top
C165  10uF  [SC0603-TD]  45.72 117.47 90 top
C166  5pF  [SC0402-PA]  61.92 44.75 270 top
C167  22uF  [SC0805-TD]  51.18 117.35 270 top
C168  100nF  [SC0402-PB]  69.65 113.54 0 top
C169  100nF  [SC0402-PB]  69.65 112.52 0 top
C170  100nF  [SC0402-PB]  51.18 113.29 180 top
C171  100nF  [SC0402-PB]  51.18 112.37 180 top
C172  100nF  [SC0402-PB]  74.8 112.5 0 top
C173  100nF  [SC0402-PB]  74.8 113.41 0 top
C174  5pF  [SC0402-PA]  62.78 44.75 270 top
C175  10uF  [SC0603-TD]  86.87 109.59 90 top
C176  100nF  [SC0402-PB]  88.07 109.72 90 top
C177  1nF  [SC0402-PA]  77.98 112.54 90 top
C178  5pF  [SC0402-PA]  63.65 44.75 270 top
C179  220pF  [SC0402-PA]  78.99 112.54 90 top
C180  100nF  [SC0402-PB]  94.04 85.85 0 top
C181  10uF  [SC0603-TD]  107.57 72.16 0 top
C182  10uF  [SC0805-TD]  121.78 108.64 0 top
C183  100nF  [SC0603-TC]  121.62 110.3 0 top
C184  22pF  [SC0402-PA]  124.38 108.07 90 top
C185  100nF  [SC0402-PB]  9.65 42.47 270 top
C186  100nF  [SC0402-PB]  11.18 39.8 180 top
C187  100nF  [SC0402-PB]  11.18 40.94 180 top
C188  100nF  [SC0402-PB]  10.62 42.47 270 top
C189  1uF  [SC0402-PC]  8 39.8 180 top
C190  1uF  [SC0402-PC]  8 40.94 180 top
C191  1uF  [SC0402-PC]  8.66 42.47 90 top
C192  1nF  [SC1206E]  3.48 19.35 270 top
C193  100nF  [SC0402-PB]  30.83 40.65 180 top
C194  100nF  [SC0402-PB]  30.83 42.47 180 top
C195  100nF  [SC0402-PB]  30.83 44.35 180 top
C196  100nF  [SC0402-PB]  30.83 41.56 180 top
C197  1uF  [SC0402-PC]  30.83 43.41 0 top
C198  1uF  [SC0402-PC]  30.83 45.44 0 top
C199  1uF  [SC0402-PC]  30.83 39.71 0 top
C200  1nF  [SC1206E]  7.39 17.2 270 top
C201  10nF  [SC0402-PB]  3.1 15.37 180 top
C202  10nF  [SC0402-PB]  31.67 21.08 180 top
C203  10nF  [SC0402-PB]  31.67 24.03 180 top
C204  10nF  [SC0402-PB]  31.67 22.1 180 top
C205  10uF  [SC0603-TD]  107.57 74.87 0 top
C206  100nF  [SC0402-PB]  97.66 86.87 90 top
C207  100nF  [SC0402-PB]  88.52 75.44 180 top
C208  100nF  [SC0402-PB]  92.08 74.04 270 top
C209  10nF  [SC0402-PB]  103.66 75.74 270 top
C210  10uF  [SC0603-TD]  107.57 73.52 180 top
C211  100nF*  [SC0603-TC]  111.33 24.08 0 top
C212  100nF  [SC0603-TC]  98.02 36.85 180 top
C213  10nF*  [SC0402-PB]  107.31 38.68 0 top
C214  100nF  [SC0402-PB]  98.25 41.66 270 top
C215  100nF  [SC0603-TC]  107.85 36.93 270 top
C216  100nF  [SC0603-TC]  118.03 18.34 0 top
C217  1uF  [SC0805-TD]  118.31 20.93 0 top
C218  100nF  [SC0603-TC]  115.24 18.34 0 top
C219  100nF  [SC0603-TC]  98.02 38.1 180 top
C220  4.7uF  [SC0603-TD]  96.2 88.71 0 top
C221  1nF*  [SC0402-PA]  98.3 40.22 180 top
C222  10uF  [SC0805-TD]  108.05 32.71 270 top
C223  10uF  [SC0805-TD]  101.53 33.23 0 top
C224  10uF  [SC0805-TD]  101.53 31.48 0 top
C225  10uF  [SC0805-TD]  106.29 32.71 270 top
C226  100nF  [SC0603-TC]  107.29 40.58 270 top
C227  100nF  [SC0402-PB]  96.27 86.87 90 top
C228  10uF  [SC0805-TD]  33.83 43.82 90 top
C229  1nF  [SC0402-PA]  42.33 44.35 90 top
C230  1nF  [SC0402-PA]  32.42 43.69 90 top
C231  10uF  [SC0805-TD]  39.09 43.82 90 top
C232  10uF  [SC0805-TD]  37.34 43.82 90 top
C233  1nF  [SC0402-PA]  82.88 19.43 270 top
C234  22pF  [SC0402-PA]  83.82 21.26 270 top
C235  1nF  [SC0402-PA]  80.31 23.3 270 top
C236  100nF  [SC0603-TC]  79.19 23.16 270 top
C237  4.7nF  [SC0402-PB]  83.21 28.62 270 top
C238  100nF  [SC0402-PB]  94.92 22.99 270 top
C239  22pF  [SC0402-PA]  80.16 21.26 270 top
C240  1uF  [SC0402-PC]  84.33 27.21 0 top
C241  10uF  [SC0805-TD]  79.96 25.96 90 top
C242  10nF  [SC0402-PB]  84.78 21.26 270 top
C243  100nF  [SC0402-PB]  85.69 19.43 270 top
C244  4.7nF  [SC0402-PB]  83.82 19.43 270 top
C245  10uF  [SC0603-TD]  103.63 79.73 90 top
C246  100nF  [SC0402-PB]  98.04 73.66 270 top
C247  22uF  [SC0805-TD]  92.96 29.06 0 top
C248  22uF  [SC0805-TD]  92.96 30.81 0 top
C249  10uF  [SC0805-TD]  78.2 25.96 90 top
C250  22pF  [SC0402-PA]  75.72 21.67 0 top
C251  100nF  [SC0402-PB]  71.54 18.24 90 top
C252  100nF  [SC0402-PB]  99.06 73.66 270 top
C253  10uF  [SC0603-TD]  105.16 79.73 90 top
C254  22uF  [SC1206-TF]  68.35 24.71 0 top
C255  22uF  [SC1206-TF]  68.35 22.5 0 top
C256  100nF  [SC0402-PB]  67.05 27.15 180 top
C257  1nF  [SC0402-PA]  73.15 20.45 0 top
C258  100nF  [SC0603-TC]  72.98 21.62 0 top
C259  10uF  [SC0805-TD]  72.62 25.58 90 top
C260  100nF  [SC0402-PB]  75.62 23.14 90 top
C261  10uF  [SC0805-TD]  74.38 25.58 90 top
C262  100nF  [SC0402-PB]  84.79 32.66 90 top
C263  10uF  [SC0603-TD]  92.81 34.49 90 top
C264  10nF  [SC0402-PB]  23.37 73.91 180 top
C265  10nF  [SC0402-PB]  65.46 34.09 0 top
C266  22uF  [SC0805-TD]  94.02 37.67 270 top
C267  100nF  [SC0603-TC]  91.15 34.47 90 top
C268  100nF  [SC0603-TC]  92.36 37.67 270 top
C269  10nF  [SC0402-PB]  88.36 38.74 90 top
C270  10uF  [SC0603-TD]  94.58 34.49 90 top
C271  10nF  [SC0402-PB]  86.93 32.97 180 top
C272  100nF  [SC0402-PB]  104.01 77.58 270 top
C273  10nF  [SC0402-PB]  73.43 40.82 270 top
C274  10nF  [SC0402-PB]  80.67 41.71 270 top
C275  10nF  [SC0402-PB]  99.19 18.67 0 top
C276  100nF  [SC0402-PB]  69.85 38.99 0 top
C277  100nF  [SC0402-PB]  76.1 41.71 270 top
C278  100nF  [SC0402-PB]  102.62 77.58 270 top
C279  100nF  [SC0402-PB]  91.06 74.04 270 top
C280  10nF  [SC0402-PB]  87.91 40.69 270 top
C281  10nF  [SC0402-PB]  95.15 40.69 270 top
C282  10nF  [SC0402-PB]  99.19 17.42 0 top
C283  100nF  [SC0402-PB]  83.34 40.69 270 top
C284  100nF  [SC0402-PB]  90.57 40.69 270 top
C285  100nF  [SC0402-PB]  131.89 32.44 180 top
C286  100nF  [SC0402-PB]  131.89 21.26 180 top
C287  100nF  [SC0402-PB]  131.89 26.85 180 top
C288  1uF  [SC0402-PC]  97.79 43.03 180 top
C289  33nF  [SC0402-PB]  98.17 44.93 270 top
C290  100nF  [SC0402-PB]  113.31 101.35 180 top
C291  100nF  [SC0402-PB]  96.81 118.38 0 top
C292  100nF  [SC0402-PB]  87.76 118.59 0 top
C293  1uF  [SC0402-PC]  110.9 91.62 270 top
C294  100nF  [SC0402-PB]  109.8 91.62 270 top
C295  100nF  [SC0402-PB]  84.32 75.49 270 top
C296  100nF  [SC0402-PB]  117.51 69.25 270 top
C297  100nF  [SC0402-PB]  100.08 73.66 270 top
C298  100nF  [SC0402-PB]  117.99 57.71 270 top
C299  100nF  [SC0402-PB]  111.44 58.55 90 top
C300  100nF  [SC0402-PB]  117.4 66.85 90 top
C301  100nF  [SC0402-PB]  110.95 69.25 270 top
C302  4.7uF  [SC0603-TD]  107.14 78.26 270 top
C303  100nF  [SC0402-PB]  111.4 78.52 90 top
C304  100nF  [SC0402-PB]  111.95 69.25 270 top
C305  100nF  [SC0402-PB]  101.6 77.58 270 top
C306  1nF  [SC0402-PA]  109.41 32.21 90 top
C307  100pF  [SC0402-PA]  74.27 95.96 270 top
C308  100nF  [SC0402-PB]  109.93 17.17 90 top
C309  10uF  [SC0805-TD]  115.19 106.2 0 top
C310  100nF  [SC0402-PB]  109.02 17.17 90 top
C311  100nF  [SC0402-PB]  75.31 92.2 180 top
C312  100pF  [SC0402-PA]  107.44 88.65 0 top
C313  100nF  [SC0402-PB]  107.44 84.07 180 top
C314  22pF  [SC0402-PA]  67.41 92.46 270 top
C317  22pF  [SC0402-PA]  69.72 89.43 180 top
C318  100nF*  [SC0402-PB]  19.94 112.78 0 top
C321  1nF  [SC0402-PA]  110.72 112.99 270 top
C322  10uF  [SC0805-TD]  35.58 43.82 90 top
C323  100nF*  [SC0402-PB]  81.53 102.11 90 top
C324  100nF*  [SC0402-PB]  98.55 103.5 180 top
C325  100nF*  [SC0402-PB]  95.17 98.37 90 top
C326  100nF*  [SC0402-PB]  96.09 98.37 90 top
C327  100nF*  [SC0402-PB]  94.56 100.12 180 top
C328  100nF*  [SC0402-PB]  79.5 102.11 90 top
C329  100nF*  [SC0402-PB]  98.55 102.49 0 top
C330  100nF*  [SC0402-PB]  81.07 99.82 180 top
C331  100nF*  [SC0402-PB]  81.92 97.66 180 top
C332  100nF*  [SC0402-PB]  88.52 107.47 270 top
C333  100nF*  [SC0402-PB]  84.35 91.92 270 top
C334  100nF*  [SC0402-PB]  91.92 104.9 90 top
C335  100nF*  [SC0402-PB]  81.07 100.84 180 top
C336  100nF*  [SC0402-PB]  80.52 102.11 90 top
C337  100nF*  [SC0402-PB]  88.01 91.92 270 top
C338  100nF*  [SC0402-PB]  87.09 91.92 270 top
C339  100nF*  [SC0402-PB]  94.26 98.37 270 top
C340  100nF*  [SC0402-PB]  94.36 91.57 270 top
C341  100nF*  [SC0402-PB]  86.18 91.92 90 top
C342  100nF*  [SC0402-PB]  95.38 104.01 270 top
C343  18pF*  [SC0402-PA]  86.11 89.15 270 top
C344  18pF*  [SC0402-PA]  81.53 89.15 90 top
C345  100nF*  [SC0402-PB]  98.68 101.22 0 top
C346  4.7uF  [SC0603-TD]  98.55 100.05 180 top
C347  4.7uF  [SC0603-TD]  98.42 97.28 180 top
C348  100nF*  [SC0402-PB]  94.36 104.01 90 top
C349  100nF*  [SC0402-PB]  83.26 105.54 180 top
C350  100nF*  [SC0402-PB]  83.26 103.71 180 top
C351  100nF*  [SC0402-PB]  83.26 104.62 180 top
C352  4.7uF*  [SC0603-TD]  98.55 98.68 0 top
C353  100nF*  [SC0402-PB]  81.92 96.65 0 top
C354  100nF*  [SC0402-PB]  98.55 104.52 180 top
C355  4.7uF*  [SC0603-TD]  96.16 106.43 270 top
C356  4.7uF*  [SC0603-TD]  94.86 106.43 270 top
C357  10uF*  [SC0603-TD]  78.54 97.79 180 top
C358  10uF*  [SC0603-TD]  78.54 96.14 180 top
C359  10uF*  [SC0603-TD]  78.54 99.44 180 top
C360  4.7uF*  [SC0603-TD]  78.54 89.69 0 top
C361  4.7uF*  [SC0603-TD]  78.54 88.37 0 top
C362  100nF*  [SC0402-PB]  95.38 91.57 270 top
C363  100nF*  [SC0402-PB]  85.27 91.92 270 top
C364  10uF*  [SC0603-TD]  78.54 94.49 180 top
C365  10uF*  [SC0603-TD]  78.54 91.19 180 top
C366  10uF*  [SC0603-TD]  78.54 92.84 180 top
C367  1uF*  [SC0402-PD]  89.79 105.92 180 top
C368  4.7uF*  [SC0603-TD]  98.42 95.76 0 top
C369  4.7uF*  [SC0603-TD]  98.58 91.14 180 top
C370  4.7uF*  [SC0603-TD]  98.58 92.53 180 top
C371  100nF  [SC0402-PB]  88.04 81.33 180 top
C372  100nF*  [SC0402-PB]  87.22 81.33 0 top
C373  100nF  [SC0402-PB]  92.64 71.25 270 top
C374  100nF*  [SC0402-PB]  92.64 70.43 90 top
C375  100nF  [SC0402-PB]  93.98 71.25 270 top
C376  100nF*  [SC0402-PB]  93.98 70.43 90 top
D1  SCHOKITTY-041-70V  [SOT23]  20.42 75.44 90 top
D2  D2-3_D  [SOT23]  58.05 24.01 270 top
D3  LED  [HSD0603-LED]  99.5 15.9 0 top
D4  NONE  [MLF10B-050-0301L]  106.98 9.78 180 top
D5  DZ_A  [HSOD523]  99.45 11.61 270 top
D6  NONE  [MLF10B-050-0301L]  110.17 9.78 180 top
D7  D_A  [SD1107S]  102.64 18.39 270 top
D9  NONE  [MLF10B-050-0301L]  42.65 23.32 0 top
D10  NONE  [MLF10B-050-0301L]  37.93 23.38 0 top
D13  NONE  [MLF10B-050-0301L]  69.17 13.25 315 top
D15  NONE  [MLF10B-050-0301L]  65.02 13.41 0 top
D17  NONE  [SOT23]  63.7 26.9 180 top
D18  NONE  [SOT23]  68.83 33.35 90 top
D21  NONE  [MLF10B-050-0301L]  90.63 13.61 0 top
D23  NONE  [MLF10B-050-0301L]  87.58 13.61 0 top
D25  NONE  [SOT23]  75.95 10.21 0 top
D27  NONE  [HSOT363-A]  131.47 39.29 0 top
D29  D_A  [SD0503A]  113.85 104.6 0 top
D30  D_A  [SD0503A]  121.67 111.68 180 top
D31  D_A  [SD0503A]  123.57 110.99 90 top
D32  D_A  [SD1107S]  118.16 111.51 180 top
D33  SLVU28_4  [SOP8-50-173]  3.84 42.54 0 top
D34  SLVU28_4  [SOP8-50-173]  15.04 42.54 0 top
D35  NONE  [SD1710A]  118.95 15.87 0 top
D40  SLVU28_4  [SOP8-50-173]  26.93 42.54 0 top
D41  D_A  [SD2211]  102.74 36.07 0 top
D43  SLVU28_4  [SOP8-50-173]  20.66 42.54 0 top
F1  NONE  [SF6127]  124.03 18.81 270 top
F3  NONE  [SF2-0302A]  114.12 15.04 90 top
ICT1  NONE  [HOLE125]  12.7 117.35 0 top
ICT2  NONE  [HOLE125]  131.25 12.88 0 top
ID1  NONE  [ID-BOARD]  2.11 109.26 0 top
ID2  NONE  [ID-BOARD]  127.46 12.14 0 top
ID3  NONE  [ID-BOARD]  2.51 11.73 0 top
J1  NONE  [CARD75-2207]  118.24 34.14 270 top
J2  NONE  [CARD75-2206A]  12.93 81.28 180 top
J3  NONE  [HSDC10-1614B]  8.81 95.88 270 top
J4  NONE  [RUSB24-050-1009]  105.85 2.48 0 top
J5  NONE  [RUSB18-200-1524A]  39.95 8.7 0 top
J6  NONE  [RUSB19-050-1512]  64.37 5.1 0 top
J7  NONE  [RUSB19-050-1512]  87.48 5.1 0 top
J8  NONE  [RWBC0104-98T-A]  118.63 116.33 180 top
J9  NONE  [RPWC0103-RM-C]  119.23 3.77 0 top
J10  NONE  [FPC51-24E]  2.47 66.15 270 top
J11  NONE  [SHEAD0220-100-100T-C]  130.02 84.58 90 top
J16  NONE  [SDIM02161-20B]  67.5 52.46 180 top
J17  NONE  [RMJ2-0201SRL]  19.32 11.06 0 top
L1  2.2uH  [SL0806A]  8.1 60.27 270 top
L2  2.2uH  [SL0806A]  55.75 40.16 270 top
L3  1uH  [SL1008H]  118.02 109 0 top
L4  470n  [SPL0707N]  89.79 24.36 0 top
L5  2.2uH  [SPL0404L]  68.25 19.08 180 top
L6  4.7uH  [SPL0302E]  110.13 81.48 270 top
L7  4.7uH*  [SPL0302E]  74.42 101.07 0 top
LB1  NONE  [SL0402C]  8.53 68.15 180 top
LB2  NONE  [SL0402C]  6.95 48.49 0 top
LB3  NONE  [SL0402C]  3.81 47.88 0 top
LB4  NONE  [SL0402C]  51.18 27.91 0 top
LB5  NONE  [SL0402C]  51.23 29.17 0 top
LB6  NONE  [SL0402C]  57.82 42.25 270 top
LB7  NONE  [SL0402C]  100.63 9.53 270 top
LB8  NONE  [SL0402C]  100.4 20.16 180 top
LB9  NONE  [SL0402C]  45.77 30.07 270 top
LB10  NONE  [SL0402C]  56.9 15.52 270 top
LB11  NONE  [SL0402C]  129.73 40.99 90 top
LB12  NONE  [SL0402C]  133.41 38.76 90 top
LB13  NONE  [SL0402C]  44.58 113.03 0 top
LB14  NONE  [SL0402C]  47.62 118.24 0 top
LB15  NONE  [SL0402C]  83.64 111.48 90 top
LB16  NONE  [SL0402C]  33.96 27.69 0 top
LB17  NONE  [SL0402C]  33.96 24.64 0 top
LB18  NONE  [SL0805]  105.54 72.9 90 top
LB19  *  [SL0805]  98.55 94.11 180 top
LB20  *  [SL0402C]  92.86 105.92 90 top
LED1  NONE  [SDA4-0606]  96.26 18.85 180 top
LED3  NONE  [SDA4-0606]  96.26 16.24 180 top
LED4  NONE  [SDA4-0606]  96.26 13.62 180 top
M1  NONE  [RHOLE189-254]  29.75 64.11 0 top
M2  NONE  [RHOLE189-254]  105.25 64.11 0 top
M3  NONE  [RHOLE189-254]  29.75 108.11 0 top
M4  NONE  [RHOLE189-254]  105.25 108.11 0 top
M5  NONE  [HOLE138-M3]  131 116 0 top
M6  NONE  [HOLE138-M3]  4 116 0 top
M7  NONE  [HOLE138-M3]  4 4 0 top
M8  NONE  [HOLE138-M3]  131 4 0 top
M9  NONE  [HOLE177]  67.5 66.18 0 top
M10  NONE  [RHOLE168-T244B188]  77.14 34.15 0 top
M11  NONE  [RHOLE168-T244B188]  12.93 110.55 0 top
M12  NONE  [RHOLE168-T244B188]  39.14 34.15 0 top
MIC1  NONE  [SBEEP3-0302]  130.58 36.63 180 top
NOREF  -  []  126.38 119.52 0 top
NOREF#2  -  []  115.95 116.01 0 top
NOREF#3  -  []  2.73 100.38 0 top
NOREF#4  -  []  134.65 7.61 0 top
NOREF#5  -  []  131.89 115.66 0 top
NOREF#6  -  []  36.02 100.05 0 top
NOREF#7  -  []  63.24 88.3 0 top
NOREF#8  -  []  44.83 99.2 0 top
NOREF#9  -  []  131.46 18.45 0 top
NOREF#10  -  []  112.82 21.25 0 top
NOREF#11  -  []  2.3 23.14 0 top
NOREF#12  -  []  110.23 37.64 0 top
NOREF#13  -  []  302.64 180.87 0 top
NOREF#14  -  []  109.89 39.98 0 top
NOREF#15  -  []  267.39 136.14 0 top
NOREF#16  -  []  -95.76 -153.01 0 top
NOREF#17  -  []  225.11 86.28 0 top
NOREF#18  -  []  121.57 11.45 0 top
NOREF#19  -  []  302.64 216.43 0 top
NOREF#20  -  []  116.76 109 0 top
NOREF#21  -  []  8.08 2.25 0 top
NOREF#22  -  []  106.1 23.09 0 top
NOREF#23  -  []  58.14 102.48 0 top
NOREF#24  -  []  58.83 84.74 0 top
NOREF#25  -  []  0 113.21 0 top
NOREF#26  -  []  56.26 253.26 0 top
NOREF#27  -  []  106.22 36.2 0 top
NOREF#28  -  []  6.81 0 90 top
NOREF#29  -  []  88.14 104.03 0 top
NOREF#30  -  []  58.14 102.48 180 bottom
NOREF#31  -  [unnamed#2]  3.2 23.11 180 bottom
NOREF#32  -  [unnamed#2]  130.56 18.54 180 bottom
NOREF#33  -  []  91.8 93.94 270 bottom
NOREF#34  -  [unnamed#2]  88.47 103.12 180 bottom
NOREF#35  -  [unnamed#2]  3.63 100.33 180 bottom
OSC1  50MHz*  [SX4-0302Q]  84.2 116.46 90 top
Q1  FETN-GSD  [SOT523-3A]  75.31 94.23 0 top
Q2  PMOS-GSD  [SOT23-3]  56.01 94.23 180 top
Q3  PMOS-GSD  [SOT23-3]  37.85 115.95 0 top
Q4  NPN-BEC  [SOT23]  51.82 98.42 180 top
Q5  NPN-BEC  [SOT23]  41.27 112.93 180 top
Q6  FETN-GSD  [SOT523-3A]  106.55 86.87 90 top
Q8  NPN-BEC  [SOT23]  97.62 32.03 270 top
Q10  NPN-BEC  [SOT23]  119.03 105.79 0 top
Q11  MOS_SGD  [RF8-NXP-PSMN1R0]  106.15 27.13 180 top
Q12  NPN-BEC  [SOT23]  71.12 42.16 0 top
Q13  NPN-BEC  [SOT23]  78.36 42.8 0 top
Q14  NPN-BEC  [SOT23]  85.6 41.78 0 top
Q15  NPN-BEC  [SOT23]  92.84 41.78 0 top
Q16  NPN-BEC  [SOT23]  108.28 44.48 0 top
R1  1k  [SR0402-TA]  41.53 117.53 180 top
R2  1k*  [SR0402-TA]  41.53 118.54 180 top
R3  33  [SR0402-TA]  75.1 117.88 270 top
R4  4.7k  [SR0402-TA]  84.56 113.65 0 top
R5  33  [SR0402-TA]  121.22 69.25 90 top
R6  33  [SR0402-TA]  110.11 73.13 0 top
R7  33  [SR0402-TA]  115.31 69.25 90 top
R8  10k  [SR0402-TA]  96.14 45.06 270 top
R9  10k  [SR0402-TA]  97.16 45.06 270 top
R10  2k  [SR0402-TA]  85.67 32.66 270 top
R11  0*  [SR0402-TA]  108.88 113.75 270 top
R12  4.7k  [SR0402-TA]  118.4 69.25 270 top
R13  100*  [SR0402-TA]  123.14 30.12 270 top
R14  1k  [SR0402-TA]  102.18 26.31 90 top
R15  4.7k  [SR0402-TA]  124.28 24.86 180 top
R16  33  [SR0402-TA]  123.27 26.88 180 top
R17  1k*  [SR0402-TA]  123.27 26.02 0 top
R18  1k  [SR0402-TA]  102.18 24.36 90 top
R19  33  [SR0402-TA]  116.42 69.25 90 top
R20  4.7k  [SR0402-TA]  73.8 88.57 180 top
R21  33  [SR0402-TA]  110.11 75.31 0 top
R22  33  [SR0402-TA]  113.54 35.81 90 top
R23  33  [SR0402-TA]  112.88 31.46 180 top
R24  4.7k*  [SR0402-TA]  111.76 37.85 90 top
R25  1k  [SR0402-TA]  110.74 37.85 90 top
R26  1k*  [SR0402-TA]  112.88 30.6 180 top
R27  1k*  [SR0402-TA]  112.64 32.95 90 top
R28  1k*  [SR0402-TA]  112.88 28.04 180 top
R29  33  [SR0402-TA]  110.11 74.3 180 top
R30  0  [SR0402-TA]  111.58 35.15 0 top
R31  0  [SR0402-TA]  111.58 36.17 0 top
R32  4.7k  [SR0402-TA]  113.55 32.95 90 top
R33  4.7k  [SR0402-TA]  112.88 28.89 180 top
R34  4.7k  [SR0402-TA]  112.88 29.75 180 top
R35  1k  [SR0402-TA]  100.33 58.93 180 top
R36  4.7k  [SR0402-TA]  124.09 67.06 0 top
R37  0*  [SR0402-TA]  14.47 87.38 270 top
R38  0*  [SR0402-TA]  10.36 87.38 270 top
R39  4.7k  [SR0402-TA]  7.86 87.38 90 top
R40  100*  [SR0402-TA]  9.14 76.07 180 top
R41  4.7k  [SR0402-TA]  5.61 75.95 90 top
R42  4.7k  [SR0402-TA]  6.48 75.95 90 top
R43  33  [SR0402-TA]  4.45 75.95 90 top
R44  33  [SR0402-TA]  17.02 87.38 90 top
R45  33  [SR0402-TA]  19.94 87.38 90 top
R46  33  [SR0402-TA]  5.69 104.58 180 top
R47  33  [SR0402-TA]  2.03 104.58 180 top
R48  4.7k  [SR0402-TA]  18.9 89.53 90 top
R49  4.7k  [SR0402-TA]  2.03 105.44 0 top
R50  4.7k  [SR0402-TA]  5.69 105.44 0 top
R51  33  [SR0402-TA]  124.09 68.26 0 top
R52  5.1k  [SR0402-TA]  75.72 20.66 0 top
R53  33  [SR0402-TA]  118.8 80.92 90 top
R54  330  [SR0402-TA]  93.28 14.13 0 top
R55  33  [SR0402-TA]  20.95 87.38 90 top
R56  33  [SR0402-TA]  124.09 89.12 180 top
R57  33  [SR0402-TA]  124.09 75.51 180 top
R58  33  [SR0402-TA]  5.29 87.38 90 top
R59  33  [SR0402-TA]  7 87.38 90 top
R60  4.7K  [SR0402-TA]  6.15 87.38 270 top
R61  4.7K  [SR0402-TA]  4.44 87.38 270 top
R62  33  [SR0402-TA]  18.92 87.38 90 top
R63  33  [SR0402-TA]  17.91 87.38 90 top
R64  4.7K  [SR0402-TA]  124.15 62.63 180 top
R65  4.7K  [SR0402-TA]  123.98 73.59 180 top
R66  4.7k  [SR0402-TA]  3.71 105.44 0 top
R67  4.7k  [SR0402-TA]  7.32 105.44 0 top
R68  33  [SR0402-TA]  3.71 104.58 180 top
R69  33  [SR0402-TA]  7.32 104.58 180 top
R70  33  [SR0402-TA]  7.49 75.95 90 top
R71  33*  [SR0402-TA]  26.04 88.34 90 top
R72  33*  [SR0402-TA]  25.97 94.06 90 top
R73  33*  [SR0402-TA]  24.77 88.34 90 top
R74  33*  [SR0402-TA]  24.7 94.06 90 top
R75  33*  [SR0402-TA]  23.5 88.34 90 top
R76  33*  [SR0402-TA]  23.43 94.06 90 top
R77  33*  [SR0402-TA]  22.16 94.06 90 top
R78  33  [SR0402-TA]  21.36 90.15 270 top
R79  33  [SR0402-TA]  22.16 93.24 270 top
R80  10k  [SR0402-TA]  22.23 87.53 270 top
R81  33  [SR0402-TA]  23.43 93.24 270 top
R82  33  [SR0402-TA]  23.5 87.53 270 top
R83  33  [SR0402-TA]  24.7 93.24 270 top
R84  33  [SR0402-TA]  24.77 87.53 270 top
R85  33  [SR0402-TA]  25.97 93.24 270 top
R86  33  [SR0402-TA]  26.04 87.53 270 top
R87  4.7k*  [SR0402-TA]  53.49 64.1 180 top
R88  4.7k*  [SR0402-TA]  53.49 66.27 180 top
R89  1k  [SR0402-TA]  6.57 56.51 180 top
R90  10k  [SR0402-TA]  45.42 40.16 90 top
R91  2.49k  [SR0402-TA]  2.41 52.58 270 top
R92  4.7k*  [SR0402-TA]  44.15 40.16 90 top
R93  4.7k*  [SR0402-TA]  46.69 40.16 90 top
R94  4.7k*  [SR0402-TA]  47.96 40.16 90 top
R95  4.7k*  [SR0402-TA]  49.23 40.16 90 top
R96  4.7k*  [SR0402-TA]  42.88 40.16 90 top
R97  4.7k*  [SR0402-TA]  23.52 60.68 270 top
R98  4.7k  [SR0402-TA]  22.83 62.48 90 top
R99  4.7k*  [SR0402-TA]  25.53 71.63 180 top
R100  1k  [SR0402-TA]  42.88 42.24 90 top
R101  0  [SR0402-TA]  21.81 60.68 90 top
R102  1k  [SR0402-TA]  8.52 69.24 0 top
R103  1k  [SR0402-TA]  8.52 70.24 0 top
R104  1k  [SR0402-TA]  6.57 55.65 180 top
R105  1M*  [SR0402-TA]  6.7 54.41 270 top
R106  33  [SR0402-TA]  6.7 52.7 90 top
R107  33  [SR0402-TA]  45.76 44.86 90 top
R108  33  [SR0402-TA]  46.62 44.86 90 top
R109  33  [SR0402-TA]  47.47 44.86 90 top
R110  33  [SR0402-TA]  48.33 44.86 90 top
R111  33  [SR0402-TA]  44.05 44.86 90 top
R112  33  [SR0402-TA]  44.91 44.86 90 top
R113  4.7k  [SR0402-TA]  122.17 104.72 270 top
R114  1K  [SR0402-TA]  55.88 116.84 0 top
R115  0  [SR0402-TA]  34.85 40.59 0 top
R116  0*  [SR0402-TA]  46.74 37.72 90 top
R117  1k  [SR0402-TA]  23.4 69.11 270 top
R118  1k*  [SR0402-TA]  24.26 69.11 90 top
R119  1k  [SR0402-TA]  17.78 47.33 270 top
R120  1k  [SR0402-TA]  44.15 42.24 90 top
R121  1k  [SR0402-TA]  49.83 42.24 90 top
R122  1k  [SR0402-TA]  47.96 42.24 90 top
R123  1k  [SR0402-TA]  46.69 42.24 90 top
R124  4.7k  [SR0402-TA]  22.67 60.68 270 top
R125  1k*  [SR0402-TA]  20.88 59.66 270 top
R126  4.7k*  [SR0402-TA]  25.53 73.91 180 top
R127  1k  [SR0402-TA]  23.37 72.77 180 top
R128  0  [SR0402-TA]  18.63 47.33 90 top
R129  0  [SR0402-TA]  25.53 70.48 180 top
R130  2.2  [SR0402-TB]  9.19 45.92 270 top
R131  2.2  [SR0402-TB]  8.18 45.92 270 top
R132  2.2  [SR0402-TB]  11.71 45.85 270 top
R133  2.2  [SR0402-TB]  10.69 45.85 270 top
R134  2.2  [SR0402-TB]  14.28 48.11 0 top
R135  2.2  [SR0402-TB]  14.28 47.2 0 top
R136  2.2  [SR0402-TB]  8.55 48.74 270 top
R137  2.2  [SR0402-TB]  9.49 48.74 270 top
R138  4.7k  [SR0402-TA]  23.37 71.63 180 top
R139  4.7k  [SR0402-TA]  24.08 59.36 0 top
R140  4.7k*  [SR0402-TA]  22.83 64.11 90 top
R141  4.7k*  [SR0402-TA]  45.42 42.24 90 top
R142  33  [SR0402-TA]  53.31 32.54 180 top
R143  4.7k*  [SR0402-TA]  64.57 40.72 0 top
R144  4.7k*  [SR0402-TA]  52.41 42.44 90 top
R145  4.7k  [SR0402-TA]  51.77 41.02 180 top
R146  4.7k*  [SR0402-TA]  49.35 38.48 180 top
R147  10k  [SR0402-TA]  64.57 41.63 180 top
R148  4.7k*  [SR0402-TA]  60.87 41.63 180 top
R149  4.7k*  [SR0402-TA]  67.36 43.87 180 top
R150  4.7k*  [SR0402-TA]  66.65 41.63 0 top
R151  4.7k*  [SR0402-TA]  65.46 37.6 180 top
R152  4.7k*  [SR0402-TA]  62.93 41.63 0 top
R153  4.7k*  [SR0402-TA]  51.77 40.13 0 top
R154  4.7k  [SR0402-TA]  51.77 39.24 0 top
R155  4.7k  [SR0402-TA]  53.26 42.29 270 top
R156  0*  [SR0402-TA]  69.47 36.07 90 top
R157  0  [SR0402-TA]  59.6 40.03 270 top
R158  33  [SR0402-TA]  60.75 42.83 180 top
R159  33  [SR0402-TA]  62.93 42.58 180 top
R160  33  [SR0402-TA]  65.46 39.41 0 top
R161  33  [SR0402-TA]  66.65 42.58 180 top
R162  33  [SR0402-TA]  64.97 44.7 90 top
R163  33  [SR0402-TA]  64.57 42.58 0 top
R164  1k  [SR0402-TA]  51.77 37.72 180 top
R165  1k  [SR0402-TA]  49.35 37.47 180 top
R166  1k  [SR0402-TA]  51.79 36.45 180 top
R167  1k  [SR0402-TA]  49.35 36.58 180 top
R168  0  [SR0402-TA]  54.08 40.36 270 top
R169  2.49k  [SR0402-TA]  53.7 30.51 0 top
R170  1K  [SR0402-TA]  55.88 117.69 0 top
R171  33  [SR0402-TA]  20.32 100.94 180 top
R172  1M*  [SR0402-TA]  53.31 33.4 180 top
R173  1k*  [SR0402-TA]  72.06 72.03 270 top
R174  1k  [SR0402-TA]  67.44 37.08 270 top
R175  1k*  [SR0402-TA]  68.33 36.07 270 top
R176  1k  [SR0402-TA]  67.17 35.33 270 top
R177  1k  [SR0402-TA]  62.93 40.72 180 top
R178  1k  [SR0402-TA]  65.46 38.5 0 top
R179  1k  [SR0402-TA]  66.65 40.72 180 top
R180  1k  [SR0402-TA]  65.88 43.89 270 top
R181  1k  [SR0402-TA]  60.87 40.72 0 top
R182  0  [SR0402-TA]  65.46 36.74 180 top
R183  0  [SR0402-TA]  65.46 35.89 180 top
R184  2.2  [SR0402-TB]  57.03 27.15 270 top
R185  2.2  [SR0402-TB]  56.13 27.15 270 top
R186  2.2  [SR0402-TB]  59.24 27.15 270 top
R187  2.2  [SR0402-TB]  58.33 27.15 270 top
R188  2.2  [SR0402-TB]  61.44 27.15 270 top
R189  2.2  [SR0402-TB]  60.54 27.15 270 top
R190  2.2  [SR0402-TB]  54.32 27.15 270 top
R191  2.2  [SR0402-TB]  55.23 27.15 270 top
R192  4.7k  [SR0402-TA]  54.12 42.44 270 top
R193  1k*  [SR0402-TA]  54.97 42.77 90 top
R194  4.7k*  [SR0402-TA]  65.46 32 180 top
R195  1k  [SR0402-TA]  65.46 33.19 0 top
R196  10k  [SR0402-TA]  54.86 92.35 270 top
R197  10k  [SR0402-TA]  56.01 97.66 270 top
R198  10k*  [SR0402-TA]  34.92 114.43 180 top
R199  10k  [SR0402-TA]  37.85 112.39 0 top
R200  1k*  [SR0402-TA]  69.5 76.28 90 top
R201  2k  [SR0402-TA]  42.3 115.87 270 top
R202  4.7k  [SR0402-TA]  44.69 80.52 90 top
R203  10k  [SR0402-TA]  45.97 80.52 90 top
R204  10k  [SR0402-TA]  9.12 87 0 top
R205  10k  [SR0402-TA]  11.6 87 180 top
R206  10k  [SR0402-TA]  15.71 87 180 top
R207  10k  [SR0402-TA]  13.23 87 0 top
R208  10k  [SR0402-TA]  42.11 80.52 90 top
R209  10k  [SR0402-TA]  40.83 80.52 90 top
R210  10k  [SR0402-TA]  39.54 80.52 90 top
R211  10k  [SR0402-TA]  38.25 80.52 90 top
R212  1k  [SR0402-TA]  50.55 101.5 270 top
R213  2k  [SR0402-TA]  51.57 101.5 270 top
R214  0  [SR0402-TA]  54.23 97.66 270 top
R215  0  [SR0402-TA]  36.45 112.9 270 top
R216  10k*  [SR0402-TA]  42.04 84.71 270 top
R217  1k*  [SR0402-TA]  69.5 72.03 90 top
R218  33*  [SR0402-TA]  13.23 87.88 180 top
R219  33*  [SR0402-TA]  15.71 87.88 0 top
R220  33*  [SR0402-TA]  11.6 87.88 0 top
R221  33*  [SR0402-TA]  9.12 87.88 180 top
R222  20k*  [SR0402-TA]  43.4 80.52 270 top
R223  10k*  [SR0402-TA]  20.07 107.95 180 top
R224  33  [SR0402-TA]  24.13 97.79 270 top
R225  33  [SR0402-TA]  24.13 99.69 270 top
R226  33  [SR0402-TA]  22.23 100.94 180 top
R227  33  [SR0402-TA]  19.56 106.17 180 top
R228  33  [SR0402-TA]  17.27 104.01 0 top
R229  47K  [SR0402-TA]  25.15 99.69 90 top
R230  47K  [SR0402-TA]  25.15 97.79 90 top
R231  47K  [SR0402-TA]  17.27 104.9 180 top
R232  47K  [SR0402-TA]  19.56 107.06 0 top
R233  47K  [SR0402-TA]  24.13 100.94 180 top
R234  100  [SR0402-TA]  22.1 106.17 0 top
R235  1k*  [SR0402-TA]  97.58 59.59 0 top
R236  4.7K  [SR0402-TA]  124.08 78.09 180 top
R237  33  [SR0402-TA]  119.88 57.71 90 top
R238  4.7K  [SR0402-TA]  124.08 77.23 180 top
R239  4.7k  [SR0402-TA]  109.98 88.77 180 top
R240  10k  [SR0402-TA]  22.1 107.06 180 top
R241  10k*  [SR0402-TA]  104.93 14.15 270 top
R242  10k  [SR0402-TA]  110.82 17.17 270 top
R243  20k*  [SR0402-TA]  105.39 17.17 90 top
R244  20k  [SR0402-TA]  100.66 12.12 90 top
R245  330  [SR0402-TA]  99.69 9.4 270 top
R246  5.1k  [SR0402-TA]  99.11 21.46 90 top
R247  20k  [SR0402-TA]  101.14 21.46 270 top
R248  1k  [SR0402-TA]  100.13 21.46 90 top
R249  20k  [SR0402-TA]  97.02 21.46 270 top
R250  10k  [SR0402-TA]  96.27 34.8 270 top
R251  4.7k  [SR0402-TA]  97.28 34.8 90 top
R252  33  [SR0402-TA]  125.93 33.66 90 top
R253  33  [SR0402-TA]  124.92 33.66 90 top
R254  4.7k  [SR0402-TA]  125.81 41.15 270 top
R255  2.2  [SR0402-TB]  67.94 15.5 270 top
R256  2.2  [SR0402-TB]  67.03 15.5 270 top
R257  0*  [SR0402-TA]  129.73 39.24 270 top
R258  33  [SR0402-TA]  123.89 103.63 0 top
R259  0  [SR0402-TA]  98.3 34.8 90 top
R260  0  [SR0402-TA]  51.05 26.42 180 top
R261  0  [SR0402-TA]  51.05 25.5 180 top
R262  0  [SR0402-TA]  41.83 26.25 270 top
R263  0  [SR0402-TA]  40.92 26.25 270 top
R264  0  [SR0402-TA]  36.22 26.25 270 top
R265  0  [SR0402-TA]  37.13 26.25 270 top
R266  0  [SR0402-TA]  51.05 24.39 180 top
R267  0  [SR0402-TA]  51.05 23.47 180 top
R268  0  [SR0402-TA]  44.3 26.25 270 top
R269  0  [SR0402-TA]  43.38 26.25 270 top
R270  0  [SR0402-TA]  38.53 26.25 270 top
R271  0  [SR0402-TA]  39.44 26.25 270 top
R272  2k  [SR0402-TA]  47.8 28.3 270 top
R273  15k  [SR0402-TA]  46.79 30.07 270 top
R274  10k  [SR0402-TA]  48.62 32.87 90 top
R275  2k  [SR0402-TA]  58.93 13.74 270 top
R276  15k  [SR0402-TA]  57.91 15.52 270 top
R277  10k  [SR0402-TA]  60.18 19.74 270 top
R278  10k  [SR0402-TA]  45.77 28.3 90 top
R279  10k  [SR0402-TA]  56.9 13.74 90 top
R280  27k  [SR0402-TA]  64.87 22.23 270 top
R281  100  [SR0402-TA]  64.87 20.07 270 top
R282  100  [SR0402-TA]  63.85 20.07 270 top
R283  100  [SR0402-TA]  62.83 20.07 270 top
R284  4.7k  [SR0402-TA]  62.83 22.23 270 top
R285  1k*  [SR0402-TA]  61.54 22.63 180 top
R286  0  [SR0402-TA]  61.54 19.58 0 top
R287  47k  [SR0402-TA]  61.54 21.62 0 top
R288  33  [SR0402-TA]  124.09 72.66 180 top
R289  33  [SR0402-TA]  124.09 85.11 0 top
R290  330  [SR0402-TA]  93.28 13.2 0 top
R291  33  [SR0402-TA]  107.57 81.3 180 top
R292  4.7K  [SR0402-TA]  125.47 57.71 90 top
R293  4.7K  [SR0402-TA]  124.54 57.71 90 top
R294  4.7K  [SR0402-TA]  123.61 57.71 90 top
R295  4.7K  [SR0402-TA]  122.67 57.71 90 top
R296  4.7k  [SR0402-TA]  63.85 22.23 270 top
R297  4.7k  [SR0402-TA]  74.85 13.89 0 top
R298  27k  [SR0402-TA]  77.06 16.1 180 top
R299  100  [SR0402-TA]  77.06 14.91 0 top
R300  100  [SR0402-TA]  77.06 13.89 0 top
R301  100  [SR0402-TA]  77.06 12.88 0 top
R302  4.7k  [SR0402-TA]  74.85 12.88 0 top
R303  1k*  [SR0402-TA]  83.36 13.46 180 top
R304  0  [SR0402-TA]  83.34 16.61 0 top
R305  47k  [SR0402-TA]  83.36 14.58 0 top
R306  4.7k  [SR0402-TA]  97.96 7.77 90 top
R307  4.7k  [SR0402-TA]  98.84 9.4 270 top
R308  301  [SR0402-TA]  24.13 102.36 180 top
R309  100  [SR0402-TA]  24.13 103.25 0 top
R310  2.2  [SR0402-TB]  69.95 15.5 270 top
R311  2.2  [SR0402-TB]  70.85 15.5 270 top
R312  2.2  [SR0402-TB]  72.49 15.5 270 top
R313  2.2  [SR0402-TB]  73.4 15.5 270 top
R314  100  [SR0402-TA]  133.17 36.12 0 top
R315  1k*  [SR0402-TA]  53.39 116.1 0 top
R316  4.7k*  [SR0402-TA]  72.39 114.81 270 top
R317  1k  [SR0402-TA]  73.41 114.81 90 top
R318  1k*  [SR0402-TA]  53.39 115.04 180 top
R319  475*  [SR0402-TA]  53.39 116.97 0 top
R320  1k  [SR0402-TA]  51.18 115.04 0 top
R321  1k  [SR0402-TA]  67.44 114.55 180 top
R322  4.7k  [SR0402-TA]  53.39 114.17 0 top
R323  33  [SR0402-TA]  67.94 112.52 0 top
R324  33  [SR0402-TA]  67.94 113.54 0 top
R325  33  [SR0402-TA]  52.83 112.37 180 top
R326  33  [SR0402-TA]  52.83 113.29 180 top
R327  33  [SR0402-TA]  73.03 113.41 0 top
R328  33  [SR0402-TA]  73.03 112.5 0 top
R329  1k  [SR0402-TA]  74.8 115.7 180 top
R330  1k  [SR0402-TA]  72.9 116.2 0 top
R331  2.2  [SR0402-TB]  64.72 15.5 270 top
R332  2.2  [SR0402-TB]  65.62 15.5 270 top
R333  49.9  [SR0402-TA]  69.65 114.55 0 top
R334  49.9  [SR0402-TA]  69.65 111.51 0 top
R335  49.9  [SR0402-TA]  74.8 114.3 0 top
R336  49.9  [SR0402-TA]  73.03 111.64 180 top
R337  49.9  [SR0402-TA]  51.18 111.48 180 top
R338  49.9  [SR0402-TA]  51.18 114.17 180 top
R339  2.2  [SR0402-TB]  84.6 16.03 270 top
R340  100  [SR0402-TA]  66.8 116.97 90 top
R341  1k  [SR0402-TA]  68.58 117.83 270 top
R342  1k  [SR0402-TA]  67.69 117.83 270 top
R343  2.2  [SR0402-TB]  85.51 16.03 270 top
R344  100  [SR0402-TA]  67.69 116.05 90 top
R345  100  [SR0402-TA]  68.58 116.05 90 top
R346  100  [SR0402-TA]  126.56 110.99 90 top
R347  10k  [SR0402-TA]  125.53 110.99 90 top
R348  4.7k*  [SR0402-TA]  112.39 105.61 0 top
R349  2.2  [SR0402-TB]  91.8 16.03 270 top
R350  100  [SR0402-TA]  111.89 104.6 180 top
R351  1k  [SR0402-TA]  116.33 104.6 0 top
R352  4.7k  [SR0402-TA]  121.31 104.72 90 top
R353  4.7k  [SR0402-TA]  121.44 106.88 90 top
R354  4.7k*  [SR0402-TA]  112.39 106.63 180 top
R355  0*  [SR0402-TA]  124.67 110.99 90 top
R356  33  [SR0402-TA]  114.78 108.03 0 top
R357  0  [SR0402-TA]  113 108.03 0 top
R358  0*  [SR0402-TA]  109.86 112.99 270 top
R359  2.2  [SR0402-TB]  92.71 16.03 270 top
R360  2.2  [SR0402-TB]  89.4 16.03 270 top
